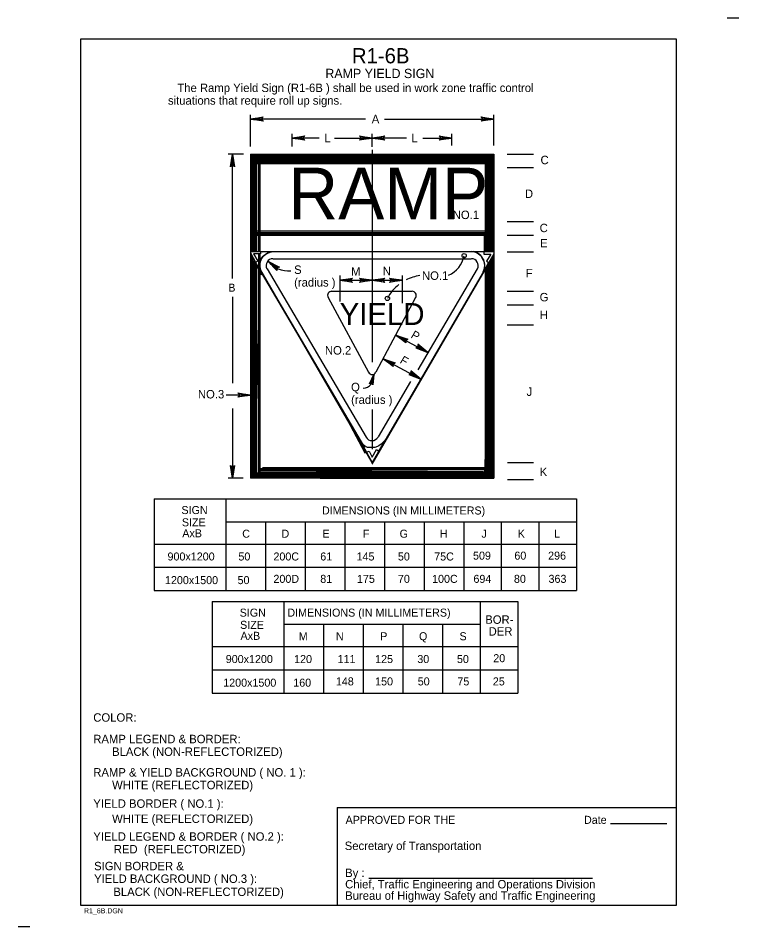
# Model space of a CAD drawing. Extents: x -0.308 to 0.195, y -0.006 to 0.263.
# Drawn here: x -0.0185 to 0.195, y -0.0064 to 0.2627 of the extents above; entities that cross this region are included whole.
import ezdxf

# ---------------------------------------------------------------- set-up
doc = ezdxf.new("R2010")
doc.units = 0
for name, color, linetype in [('1', 7, 'Continuous'), ('2', 7, 'Continuous'), ('3', 7, 'Continuous')]:
    doc.layers.add(name, color=color, linetype=linetype)

# ---------------------------------------------------------------- blocks, each defined once
blk = doc.blocks.new('RARROW')
at = {"layer": '3'}
for p, q in [((-2.156, 0.28500000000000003), (-2.2665, 0.384625)), ((-2.2665, 0.384625), (0, 0)), ((0, 0), (-2.2665, -0.379125)), ((-2.156, 0.28500000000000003), (-2.075625, 0.12075)), ((0, 0), (-2.156, 0.28500000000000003)), ((-2.14975, -0.2705), (0, 0)), ((-2.075625, 0.12075), (0, 0)), ((0, 0), (-2.074, -0.108)), ((-2.2665, -0.379125), (-2.14975, -0.2705)), ((-2.074, -0.108), (-2.14975, -0.2705))]:
    blk.add_line(p, q, dxfattribs=at)

msp = doc.modelspace()

# ---------------------------------------------------------------- linework, layer by layer
at = {"layer": '1'}
for p, q in [((0.195, 0.26275), (0.1915, 0.26275)), ((0.1765, 0.2565), (0, 0.2565)), ((0, 0.2565), (0, 0)), ((0.1765, 0), (0.1765, 0.2565)), ((0.08637500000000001, 0.22375), (0.08637500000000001, 0.160875)), ((0.07675, 0.1865), (0.07675, 0.178875)), ((0.09525, 0.1865), (0.09525, 0.178375)), ((0.08637500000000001, 0.146875), (0.08637500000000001, 0.135125)), ((0.076, 0.029), (0.1765, 0.029)), ((0.076, 0.029), (0.076, 0)), ((0.157, 0.02425), (0.173625, 0.02425)), ((0.085375, 0.008), (0.151625, 0.008)), ((0, 0), (0.1765, 0)), ((-0.015, -0.0063750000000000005), (-0.0185, -0.0063750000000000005))]:
    msp.add_line(p, q, dxfattribs=at)
at = {"layer": '3'}
for p, q in [((0.050375, 0.22475), (0.050375, 0.234125)), ((0.084375, 0.232875), (0.050375, 0.232875)), ((0.09, 0.232875), (0.122375, 0.232875)), ((0.122375, 0.225), (0.122375, 0.234125)), ((0.062625, 0.22475), (0.062625, 0.2285)), ((0.07062500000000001, 0.22725), (0.062625, 0.22725)), ((0.07525, 0.22725), (0.08637500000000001, 0.22725)), ((0.08637500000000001, 0.224625), (0.08637500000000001, 0.2285)), ((0.0965, 0.22725), (0.08637500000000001, 0.22725)), ((0.101375, 0.22725), (0.11, 0.22725)), ((0.11, 0.225), (0.11, 0.2285)), ((0.04825, 0.2225), (0.043750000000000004, 0.2225)), ((0.045, 0.185625), (0.045, 0.2225)), ((0.050375, 0.2225), (0.122375, 0.2225)), ((0.050375, 0.2225), (0.050375, 0.1265)), ((0.050375, 0.22225), (0.122375, 0.22225)), ((0.050375, 0.222), (0.122375, 0.222)), ((0.050375, 0.22175), (0.122375, 0.22175)), ((0.050375, 0.2215), (0.122375, 0.2215)), ((0.050375, 0.22125), (0.122375, 0.22125)), ((0.050375, 0.221), (0.122375, 0.221)), ((0.050375, 0.22075), (0.122375, 0.22075)), ((0.050625, 0.19375), (0.050625, 0.2225)), ((0.050875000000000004, 0.19375), (0.050875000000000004, 0.2225)), ((0.051250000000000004, 0.19375), (0.051250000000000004, 0.2225)), ((0.051500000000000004, 0.19375), (0.051500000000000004, 0.2225)), ((0.051875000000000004, 0.19375), (0.051875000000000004, 0.2225)), ((0.05225, 0.19375), (0.05225, 0.2225)), ((0.05275, 0.19375), (0.05275, 0.2225)), ((0.053125, 0.2225), (0.053125, 0.19375)), ((0.11987500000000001, 0.221), (0.11987500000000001, 0.19375)), ((0.12025, 0.221), (0.12025, 0.19375)), ((0.120625, 0.221), (0.120625, 0.193625)), ((0.120875, 0.221), (0.120875, 0.193625)), ((0.121125, 0.221), (0.121125, 0.193625)), ((0.121375, 0.221), (0.121375, 0.193625)), ((0.121625, 0.221), (0.121625, 0.19375)), ((0.121875, 0.221), (0.121875, 0.193625)), ((0.122125, 0.221), (0.122125, 0.19375)), ((0.122375, 0.2225), (0.122375, 0.1265)), ((0.12637500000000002, 0.2225), (0.134125, 0.2225)), ((0.050375, 0.2205), (0.122375, 0.2205)), ((0.050375, 0.22012500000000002), (0.122375, 0.22012500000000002)), ((0.050375, 0.21975), (0.122375, 0.21975)), ((0.12637500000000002, 0.2185), (0.134125, 0.2185)), ((0.12637500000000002, 0.2025), (0.134125, 0.2025)), ((0.051875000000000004, 0.19975), (0.120875, 0.19975)), ((0.051875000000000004, 0.19925), (0.120875, 0.19925)), ((0.051875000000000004, 0.198875), (0.120875, 0.198875)), ((0.051875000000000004, 0.1985), (0.11950000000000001, 0.1985)), ((0.12637500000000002, 0.1985), (0.134125, 0.1985)), ((0.050375, 0.193625), (0.053125, 0.193625)), ((0.050375, 0.19325), (0.053625, 0.187125)), ((0.0505, 0.192625), (0.053625, 0.18675)), ((0.050625, 0.128), (0.050625, 0.19225)), ((0.050875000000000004, 0.128), (0.050875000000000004, 0.19175)), ((0.05275, 0.128), (0.05275, 0.19275)), ((0.053125, 0.193625), (0.12225, 0.193625)), ((0.053125, 0.192875), (0.053125, 0.19062500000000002)), ((0.05375, 0.1935), (0.11950000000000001, 0.193625)), ((0.057, 0.1915), (0.11575, 0.1915)), ((0.12225, 0.1925), (0.08625000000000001, 0.130625)), ((0.122375, 0.193), (0.08637500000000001, 0.131125)), ((0.121625, 0.19112500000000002), (0.121625, 0.128)), ((0.121875, 0.19162500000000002), (0.121875, 0.128)), ((0.122125, 0.19225), (0.122125, 0.128)), ((0.12637500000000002, 0.1935), (0.134125, 0.1935)), ((0.051250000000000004, 0.128), (0.051250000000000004, 0.191)), ((0.051500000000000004, 0.128), (0.051500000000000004, 0.1905)), ((0.051875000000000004, 0.128), (0.051875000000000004, 0.19025)), ((0.05225, 0.128), (0.05225, 0.18987500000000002)), ((0.053125, 0.18862500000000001), (0.053125, 0.128)), ((0.05525, 0.1885), (0.084625, 0.138625)), ((0.11750000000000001, 0.1885), (0.099875, 0.15862500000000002)), ((0.12025, 0.18887500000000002), (0.12025, 0.128)), ((0.120625, 0.18975), (0.120625, 0.128)), ((0.120875, 0.19), (0.120875, 0.128)), ((0.121125, 0.19037500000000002), (0.121125, 0.128)), ((0.121375, 0.19087500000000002), (0.121375, 0.128)), ((0.0535, 0.18762500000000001), (0.084125, 0.135625)), ((0.0535, 0.187375), (0.082875, 0.1375)), ((0.11987500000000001, 0.18837500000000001), (0.11987500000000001, 0.128)), ((0.07675, 0.185125), (0.08637500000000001, 0.185125)), ((0.08637500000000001, 0.185125), (0.09525, 0.185125)), ((0.074375, 0.181875), (0.098125, 0.181875)), ((0.12637500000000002, 0.181875), (0.134125, 0.181875)), ((0.045, 0.18025), (0.045, 0.154625)), ((0.073375, 0.18), (0.08525, 0.15787500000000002)), ((0.09925, 0.18), (0.08750000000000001, 0.15787500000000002)), ((0.12637500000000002, 0.177875), (0.134125, 0.177875)), ((0.12637500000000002, 0.171875), (0.134125, 0.171875)), ((0.093375, 0.168875), (0.10287500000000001, 0.16375)), ((0.089625, 0.161875), (0.10075, 0.155875)), ((0.09775, 0.155125), (0.088125, 0.13875)), ((0.050375, 0.151125), (0.043125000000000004, 0.151125)), ((0.045, 0.1470964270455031), (0.045, 0.1265)), ((0.082625, 0.138), (0.08637500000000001, 0.131125)), ((0.05325, 0.129375), (0.11950000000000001, 0.129375)), ((0.053875, 0.129625), (0.120125, 0.129625)), ((0.1265, 0.131125), (0.134125, 0.131125)), ((0.048125, 0.1265), (0.043750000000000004, 0.1265)), ((0.122375, 0.128), (0.050375, 0.128)), ((0.122375, 0.12775), (0.050375, 0.12775)), ((0.122375, 0.1275), (0.050375, 0.1275)), ((0.122375, 0.12725), (0.050375, 0.12725)), ((0.122375, 0.127), (0.050375, 0.127)), ((0.122375, 0.12675), (0.050375, 0.12675)), ((0.122375, 0.1265), (0.050375, 0.1265)), ((0.05325, 0.129125), (0.11950000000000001, 0.129125)), ((0.05325, 0.128875), (0.11925000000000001, 0.1285)), ((0.05325, 0.128375), (0.11950000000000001, 0.128375)), ((0.07100000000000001, 0.1265), (0.122375, 0.1265)), ((0.1265, 0.12612500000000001), (0.134125, 0.12612500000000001)), ((0.021750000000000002, 0.120375), (0.146875, 0.120375)), ((0.021750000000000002, 0.120375), (0.021750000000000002, 0.09325)), ((0.043000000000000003, 0.120375), (0.043000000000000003, 0.09325)), ((0.146875, 0.120375), (0.146875, 0.09325)), ((0.146875, 0.1135), (0.043000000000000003, 0.1135)), ((0.05475, 0.1135), (0.05475, 0.09325)), ((0.0665, 0.1135), (0.0665, 0.09325)), ((0.07825, 0.1135), (0.07825, 0.09325)), ((0.09, 0.1135), (0.09, 0.09325)), ((0.10175000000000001, 0.1135), (0.10175000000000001, 0.09325)), ((0.1135, 0.1135), (0.1135, 0.09325)), ((0.124625, 0.1135), (0.124625, 0.09325)), ((0.13575, 0.1135), (0.13575, 0.09325)), ((0.021750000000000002, 0.107), (0.146875, 0.107)), ((0.021750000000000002, 0.100125), (0.146875, 0.100125)), ((0.021750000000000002, 0.09325), (0.146875, 0.09325)), ((0.039, 0.09), (0.1295, 0.09)), ((0.039, 0.09), (0.039, 0.062875)), ((0.06025, 0.09), (0.06025, 0.062875)), ((0.11837500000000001, 0.09), (0.11837500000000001, 0.062875)), ((0.1295, 0.09), (0.1295, 0.062875)), ((0.11837500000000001, 0.083125), (0.06025, 0.083125)), ((0.07200000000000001, 0.083125), (0.07200000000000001, 0.062875)), ((0.08375, 0.083125), (0.08375, 0.062875)), ((0.0955, 0.083125), (0.0955, 0.062875)), ((0.10725, 0.083125), (0.10725, 0.062875)), ((0.039, 0.076625), (0.1295, 0.076625)), ((0.039, 0.06975), (0.1295, 0.06975)), ((0.039, 0.062875), (0.1295, 0.062875))]:
    msp.add_line(p, q, dxfattribs=at)
for points in [[(0.053125, 0.193625), (0.11962500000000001, 0.193625), (0.11962500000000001, 0.199), (0.053125, 0.199)], [(0.05325, 0.193625), (0.05325, 0.193), (0.051250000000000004, 0.193), (0.0525, 0.19075), (0.051625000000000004, 0.19025), (0.053, 0.18862500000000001), (0.053125, 0.18875), (0.053, 0.18937500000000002), (0.053, 0.1895), (0.053125, 0.1905), (0.053375, 0.19112500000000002), (0.053625, 0.19162500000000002), (0.054125, 0.19225), (0.054875, 0.192875), (0.055625, 0.19325), (0.0565, 0.1935)], [(0.053125, 0.18862500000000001), (0.051625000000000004, 0.12775), (0.05675, 0.128375), (0.11975000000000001, 0.12825), (0.12225, 0.1925), (0.08637500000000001, 0.131125)], [(0.11950000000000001, 0.193625), (0.11950000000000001, 0.192875), (0.1215, 0.192875), (0.12025, 0.19075), (0.120875, 0.19037500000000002), (0.11925000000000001, 0.187375), (0.11962500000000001, 0.18875), (0.11975000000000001, 0.18962500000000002), (0.11975000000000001, 0.18987500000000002), (0.11962500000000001, 0.19037500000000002), (0.11937500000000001, 0.191), (0.11900000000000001, 0.19162500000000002), (0.11862500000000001, 0.19225), (0.11787500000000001, 0.192875), (0.11725000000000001, 0.19325), (0.11625, 0.193625)], [(0.08425, 0.134), (0.0855, 0.1345), (0.08637500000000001, 0.13275), (0.08762500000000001, 0.135), (0.088375, 0.1345), (0.090375, 0.138), (0.089375, 0.136875), (0.089, 0.136625), (0.088375, 0.136125), (0.088, 0.135875), (0.08712500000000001, 0.135625), (0.08637500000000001, 0.135625), (0.085, 0.135625), (0.084125, 0.136125), (0.083375, 0.136625), (0.07725, 0.147)]]:
    msp.add_lwpolyline(points, close=True, dxfattribs=at)
for centre in [(0.113625, 0.192375), (0.090875, 0.17975)]:
    msp.add_circle(centre, 0.000637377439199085, dxfattribs=at)
for centre, radius, start, end in [((0.057048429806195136, 0.1895), 0.004, 90, 208.1237361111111), ((0.05696101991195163, 0.1895), 0.002, 90, 208.11320833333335), ((0.105697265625, 0.19401660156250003), 0.008095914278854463, 294.0761694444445, 348.30106111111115), ((0.11568832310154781, 0.18957701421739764), 0.004048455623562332, 331.0033472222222, 89.12708333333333), ((0.11578898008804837, 0.1895), 0.002, 331.8867916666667, 90), ((0.06165576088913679, 0.19601600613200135), 0.008095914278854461, 220.30939722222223, 274.5342888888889), ((0.10220203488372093, 0.1738357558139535), 0.01277810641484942, 97.65450833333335, 117.01230000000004), ((0.10220203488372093, 0.1738357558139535), 0.01277810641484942, 128.53098888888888, 152.42935277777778), ((0.07443707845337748, 0.180625), 0.00125, 90.00000000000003, 207.55281111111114), ((0.09817686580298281, 0.180625), 0.00125, 332.17590277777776, 90), ((0.08352322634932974, 0.15636655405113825), 0.003249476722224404, 274.00179722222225, 6.776827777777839), ((0.08638736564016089, 0.15845147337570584), 0.00125, 207.29957222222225, 332.1759027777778), ((0.08634549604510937, 0.13962141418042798), 0.002, 208.4956388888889, 332.3005277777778)]:
    msp.add_arc(centre, radius, start, end, dxfattribs=at)

# ---------------------------------------------------------------- block references
for p, xscale, yscale, rotation in [((0.050375, 0.232875), 0.0016545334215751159, 0.0016366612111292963, 180), ((0.062625, 0.22725), 0.0016545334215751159, 0.0016366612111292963, 180), ((0.08637500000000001, 0.22725), 0.0016545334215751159, 0.0016366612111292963, 180), ((0.045, 0.2225), 0.0016545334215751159, 0.0016366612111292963, 90), ((0.0555, 0.19075), 0.0016545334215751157, 0.0016366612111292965, 143.79741070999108), ((0.07675, 0.185125), 0.0016545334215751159, 0.0016366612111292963, 180), ((0.08637500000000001, 0.185125), 0.0016545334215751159, 0.0016366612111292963, 180), ((0.093375, 0.168875), 0.0016545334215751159, 0.0016366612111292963, 151.92751306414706), ((0.10287500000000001, 0.16375), 0.0016545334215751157, -0.001636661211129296, -30.26273982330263), ((0.089625, 0.161875), 0.0016545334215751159, 0.0016366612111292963, 151.92751306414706), ((0.08687500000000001, 0.15725), 0.001340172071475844, 0.00132569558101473, 75.26029663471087), ((0.10075, 0.155875), 0.0016545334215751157, -0.001636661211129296, -30.26273982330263), ((0.045, 0.1265), 0.0016545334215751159, 0.0016366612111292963, -90)]:
    msp.add_blockref('RARROW', p, dxfattribs=dict(at, xscale=xscale, yscale=yscale, rotation=rotation))
at = {"layer": '3', "xscale": 0.0016545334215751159, "yscale": 0.0016366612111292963}
for p in [(0.122375, 0.232875), (0.08637500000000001, 0.22725), (0.11, 0.22725), (0.08637500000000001, 0.185125), (0.09525, 0.185125), (0.050375, 0.151125)]:
    msp.add_blockref('RARROW', p, dxfattribs=at)

# ---------------------------------------------------------------- texts
at = {"layer": '1'}
for s, height, p in [('R1-6B', 0.0045000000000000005, (0.080375, 0.249375)), ('RAMP YIELD SIGN', 0.00275025, (0.0725, 0.245)), ('COLOR:', 0.0024997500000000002, (0.00375, 0.054375)), ('RAMP LEGEND & BORDER:', 0.0024997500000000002, (0.00375, 0.048)), ('      BLACK (NON-REFLECTORIZED)', 0.0024997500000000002, (0.00375, 0.04425)), ('RAMP & YIELD BACKGROUND ( NO. 1 ):', 0.0024997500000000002, (0.00375, 0.038125)), ('      WHITE (REFLECTORIZED)', 0.0024997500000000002, (0.00375, 0.034375)), ('YIELD BORDER ( NO.1 ):', 0.0024997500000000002, (0.00375, 0.028875)), ('      WHITE (REFLECTORIZED)', 0.0024997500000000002, (0.00375, 0.024375)), ('APPROVED FOR THE', 0.0023752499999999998, (0.0785, 0.024125)), ('Date ', 0.0023752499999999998, (0.149125, 0.024125)), ('YIELD LEGEND & BORDER ( NO.2 ):', 0.0024997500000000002, (0.00375, 0.019125)), ('Secretary of Transportation', 0.0024997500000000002, (0.07825, 0.016375)), ('      RED  (REFLECTORIZED)', 0.0024997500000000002, (0.00425, 0.015375)), ('SIGN BORDER &', 0.0024997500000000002, (0.004, 0.010375)), ('By :', 0.0024997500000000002, (0.078375, 0.008375)), ('YIELD BACKGROUND ( NO.3 ):', 0.0024997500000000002, (0.004, 0.006625)), ('      BLACK (NON-REFLECTORIZED)', 0.0024997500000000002, (0.004125, 0.00275)), ('Chief, Traffic Engineering and Operations Division', 0.0024997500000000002, (0.078375, 0.005)), ('Bureau of Highway Safety and Traffic Engineering', 0.0024997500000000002, (0.078375, 0.0016250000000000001)), ('R1_6B.DGN', 0.0015, (0.001, -0.002375))]:
    msp.add_text(s, height=height, dxfattribs=at).set_placement(p)
at = {"layer": '2'}
for s, p in [('   The Ramp Yield Sign (R1-6B ) shall be used in work zone traffic control', (0.025875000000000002, 0.240875)), ('situations that require roll up signs.', (0.025875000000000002, 0.237125))]:
    msp.add_text(s, height=0.0024997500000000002, dxfattribs=at).set_placement(p)
at = {"layer": '3'}
for s, height, p in [('A', 0.0024997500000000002, (0.08625000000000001, 0.231625)), ('L', 0.0024997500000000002, (0.07225, 0.226)), ('L', 0.0024997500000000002, (0.098, 0.226)), ('C', 0.0024997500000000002, (0.13625, 0.2195)), ('RAMP', 0.01533, (0.0615, 0.203125)), ('D', 0.0024997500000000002, (0.131625, 0.2095)), ('NO.1', 0.0024997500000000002, (0.11025, 0.20325000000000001)), ('C', 0.0024997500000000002, (0.136, 0.199375)), ('E', 0.0024997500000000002, (0.136125, 0.194875)), ('S', 0.0024997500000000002, (0.06325, 0.187)), ('M', 0.0024997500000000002, (0.080125, 0.1865)), ('N', 0.0024997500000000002, (0.0895, 0.186625)), ('F', 0.0024997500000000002, (0.131875, 0.186)), ('(radius )', 0.0024997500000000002, (0.06325, 0.18325)), ('NO.1', 0.0024997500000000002, (0.101125, 0.18525)), ('B', 0.0023752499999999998, (0.043750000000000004, 0.18175)), ('G', 0.0024997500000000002, (0.136, 0.178875)), ('YIELD', 0.006500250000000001, (0.07675, 0.171875)), ('H', 0.0024997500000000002, (0.136, 0.173625)), ('NO.2', 0.0024997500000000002, (0.072375, 0.163125)), ('Q', 0.0024997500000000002, (0.080125, 0.15225)), ('NO.3', 0.0024997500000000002, (0.03475, 0.150125)), ('(radius )', 0.0024997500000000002, (0.080125, 0.1485)), ('J', 0.0024997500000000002, (0.132125, 0.150875)), ('K', 0.0024997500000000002, (0.136, 0.12712500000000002)), ('SIGN', 0.0023752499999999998, (0.029875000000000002, 0.115875)), ('DIMENSIONS (IN MILLIMETERS)', 0.0023752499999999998, (0.07150000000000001, 0.11575)), ('SIZE', 0.0023752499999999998, (0.03, 0.11225)), ('AxB', 0.0023752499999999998, (0.030125, 0.109)), ('C', 0.0023752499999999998, (0.047875, 0.108875)), ('D', 0.0023752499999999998, (0.059500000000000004, 0.108875)), ('E', 0.0023752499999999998, (0.07162500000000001, 0.108875)), ('F', 0.0023752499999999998, (0.083625, 0.108875)), ('G', 0.0023752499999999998, (0.0945, 0.108875)), ('H', 0.0023752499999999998, (0.106375, 0.108875)), ('J', 0.0023752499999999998, (0.11875000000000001, 0.108875)), ('K', 0.0023752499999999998, (0.1295, 0.108875)), ('L', 0.0023752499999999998, (0.14025, 0.108875)), ('900x1200', 0.0023752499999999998, (0.025750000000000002, 0.10212500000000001)), ('50', 0.0023752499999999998, (0.04675, 0.10212500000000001)), ('200C', 0.0023752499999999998, (0.057125, 0.10212500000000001)), ('61', 0.0023752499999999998, (0.07100000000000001, 0.10212500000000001)), ('145', 0.0023752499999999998, (0.08175, 0.10212500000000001)), ('50', 0.0023752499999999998, (0.094, 0.10212500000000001)), ('75C', 0.0023752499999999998, (0.10475, 0.10212500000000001)), ('509', 0.0023752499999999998, (0.11625, 0.10237500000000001)), ('60', 0.0023752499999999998, (0.1285, 0.10237500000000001)), ('296', 0.0023752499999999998, (0.1385, 0.10237500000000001)), ('1200x1500', 0.0023752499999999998, (0.025, 0.095125)), ('50', 0.0023752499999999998, (0.0465, 0.095125)), ('200D', 0.0023752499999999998, (0.057125, 0.0955)), ('81', 0.0023752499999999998, (0.07100000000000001, 0.0955)), ('175', 0.0023752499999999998, (0.081875, 0.0955)), ('70', 0.0023752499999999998, (0.094, 0.0955)), ('100C', 0.0023752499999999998, (0.104125, 0.0955)), ('694', 0.0023752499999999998, (0.116375, 0.0955)), ('80', 0.0023752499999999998, (0.128375, 0.0955)), ('363', 0.0023752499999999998, (0.138625, 0.0955)), ('SIGN', 0.0023752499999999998, (0.047125, 0.0855)), ('DIMENSIONS (IN MILLIMETERS)', 0.0023752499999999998, (0.06125, 0.0855)), ('SIZE', 0.0023752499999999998, (0.04725, 0.081875)), ('BOR-', 0.0024997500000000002, (0.11987500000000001, 0.083375)), ('AxB', 0.0023752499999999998, (0.047375, 0.078625)), ('M', 0.0023752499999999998, (0.064625, 0.0785)), ('N', 0.0023752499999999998, (0.075625, 0.0785)), ('P', 0.0023752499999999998, (0.08875, 0.0785)), ('Q', 0.0023752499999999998, (0.10025, 0.0785)), ('S', 0.0023752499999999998, (0.11225, 0.0785)), ('DER', 0.0024997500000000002, (0.120875, 0.079875)), ('900x1200', 0.0023752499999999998, (0.043000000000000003, 0.07175000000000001)), ('120', 0.0023752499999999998, (0.06325, 0.07175000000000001)), ('111', 0.0023752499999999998, (0.076125, 0.07175000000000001)), ('125', 0.0023752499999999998, (0.08725000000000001, 0.07175000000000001)), ('30', 0.0023752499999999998, (0.09975, 0.07175000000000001)), ('50', 0.0023752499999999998, (0.1115, 0.07175000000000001)), ('20', 0.0023752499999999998, (0.12225, 0.07200000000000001)), ('148', 0.0023752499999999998, (0.075625, 0.065125)), ('150', 0.0023752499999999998, (0.08725000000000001, 0.065125)), ('50', 0.0023752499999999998, (0.099875, 0.065125)), ('75', 0.0023752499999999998, (0.111625, 0.065125)), ('25', 0.0023752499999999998, (0.122125, 0.065125)), ('1200x1500', 0.0023752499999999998, (0.04225, 0.06475)), ('160', 0.0023752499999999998, (0.063, 0.06475))]:
    msp.add_text(s, height=height, dxfattribs=at).set_placement(p)
for s, height, p in [('P', 0.0024990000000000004, (0.097625, 0.16825)), ('F', 0.0024997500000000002, (0.094375, 0.16075))]:
    msp.add_text(s, height=height, rotation=329.34123611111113, dxfattribs=at).set_placement(p)

doc.saveas('drawing.dxf')
